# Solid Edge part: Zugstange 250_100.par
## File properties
Username: ahadarics
Dokumentum tartalom típus: 0
Author: ahadarics
Last saved by: ahadarics
Revision: 81
Sűrűség: 0,000 kg/m^3
Pontosság: 0,990
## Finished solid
Body 1: solid body, 5 faces, 7 edges, 4 vertices.
  Faces by surface: cone 2, plane 2, cylinder 1
  Edges by curve: circle 5, line 2
Bounding box of the edges (mm): 20.000 x 20.000 x 248.000, from (-10, -10, -161.5) to (10, 10, 86.5).
Cylindrical faces by radius (mm): R10 x1
Conical faces (half-angle, radius in mm at the cone's reference point): 45 deg R9.25 x2
Planar faces by outward normal: +z 1, -z 1
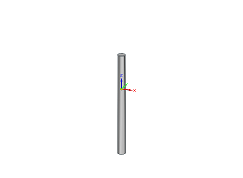
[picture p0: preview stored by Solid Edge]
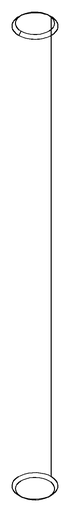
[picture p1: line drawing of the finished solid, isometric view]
